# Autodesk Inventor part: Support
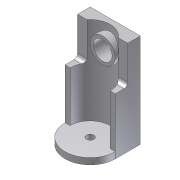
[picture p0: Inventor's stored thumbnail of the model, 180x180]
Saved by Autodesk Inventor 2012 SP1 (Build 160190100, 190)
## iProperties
Created: 2006-03
Part Number: Support
Document SubType Name: Modeling
Manufacturer: Standard
Standards Organization: Custom
Mass: 42.849 g
Surface Area: 163.994 cm^2
Volume: 42.849 cm^3
Density: 1 g/cm^3
Material: Default
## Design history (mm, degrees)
sketch "Sketch4"
  geometry: L1 (0, -24)-(0, 32) reference; L2 (-32, 0)-(24, 0) reference; L3 (20, 0)-(20, -20); L4 (20, -20)-(-20, -20); L5 (-20, -20)-(-20, 0); C1 r 3 at (0, 0); A1 r 20 centre (0, 0) between (20, 0) and (-20, 0); 1 further point
  constraints: 6 end point, 2 centre point, 2 coincident, 2 perpendicular, 2 point on circle, 2 tangent, 1 parallel, 1 point on line
  dimensions: "d7" = 20 radius of A1; "d8" = 20 distance of L3.start L3.end; "d9" = 6 diameter of C1
extrude "Extrusion3" new body sketch "Sketch4" distance "d10" = 5; taper "d11" = 0 deg
sketch "Sketch5"
  geometry: L1 (0, 24)-(0, -32) reference; L2 (32, 0)-(-24, 0) reference; L3 (-16, 0)-(-20, 0); L4 (-20, 0)-(-20, 20); L5 (-20, 20)-(20, 20); L6 (20, 20)-(20, 0); A1 r 16 centre (0, 0) between (16, 0) and (-16, 0); 1 further point
  constraints: 8 end point, 2 perpendicular, 2 point on circle, 2 point on line, 1 centre point, 1 coincident, 1 collinear, 1 parallel
  dimensions: "d14" = 16 radius of A1
extrude "Extrusion4" join sketch "Sketch5" distance "d12" = 100; taper "d13" = 0 deg
feature "Sculpt1"
  workplane "Work Plane1"
  workplane "Work Plane2"
sketch "Sketch6"
  geometry: L1 (-12.49, 31.5)-(-12.49, -115.5) reference; L2 (0, 0)-(-24.98, 0) reference; C1 r 11 at (-12.49, -15); 1 further point
  constraints: 1 centre point, 1 point on line
  dimensions: "d17" = 15 distance from line of L2 C1.centre; "d18" = 22 diameter of C1
extrude "Extrusion5" join sketch "Sketch6" stored distance "d19" = 50; taper "d20" = 0 deg
sketch "Sketch7"
  geometry: C1 r 11 at (0, 0) reference; C2 r 7.5 at (0, 0); 1 further point
  constraints: 1 centre point, 1 coincident
  dimensions: "d21" = 15 diameter of C2
extrude "Extrusion6" cut sketch "Sketch7" distance "d22" = 50; taper "d23" = 0 deg
fillet "Fillet1" dims "d24" = 3
body "Solid1"
